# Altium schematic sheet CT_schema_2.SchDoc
size 591 x 347 mm
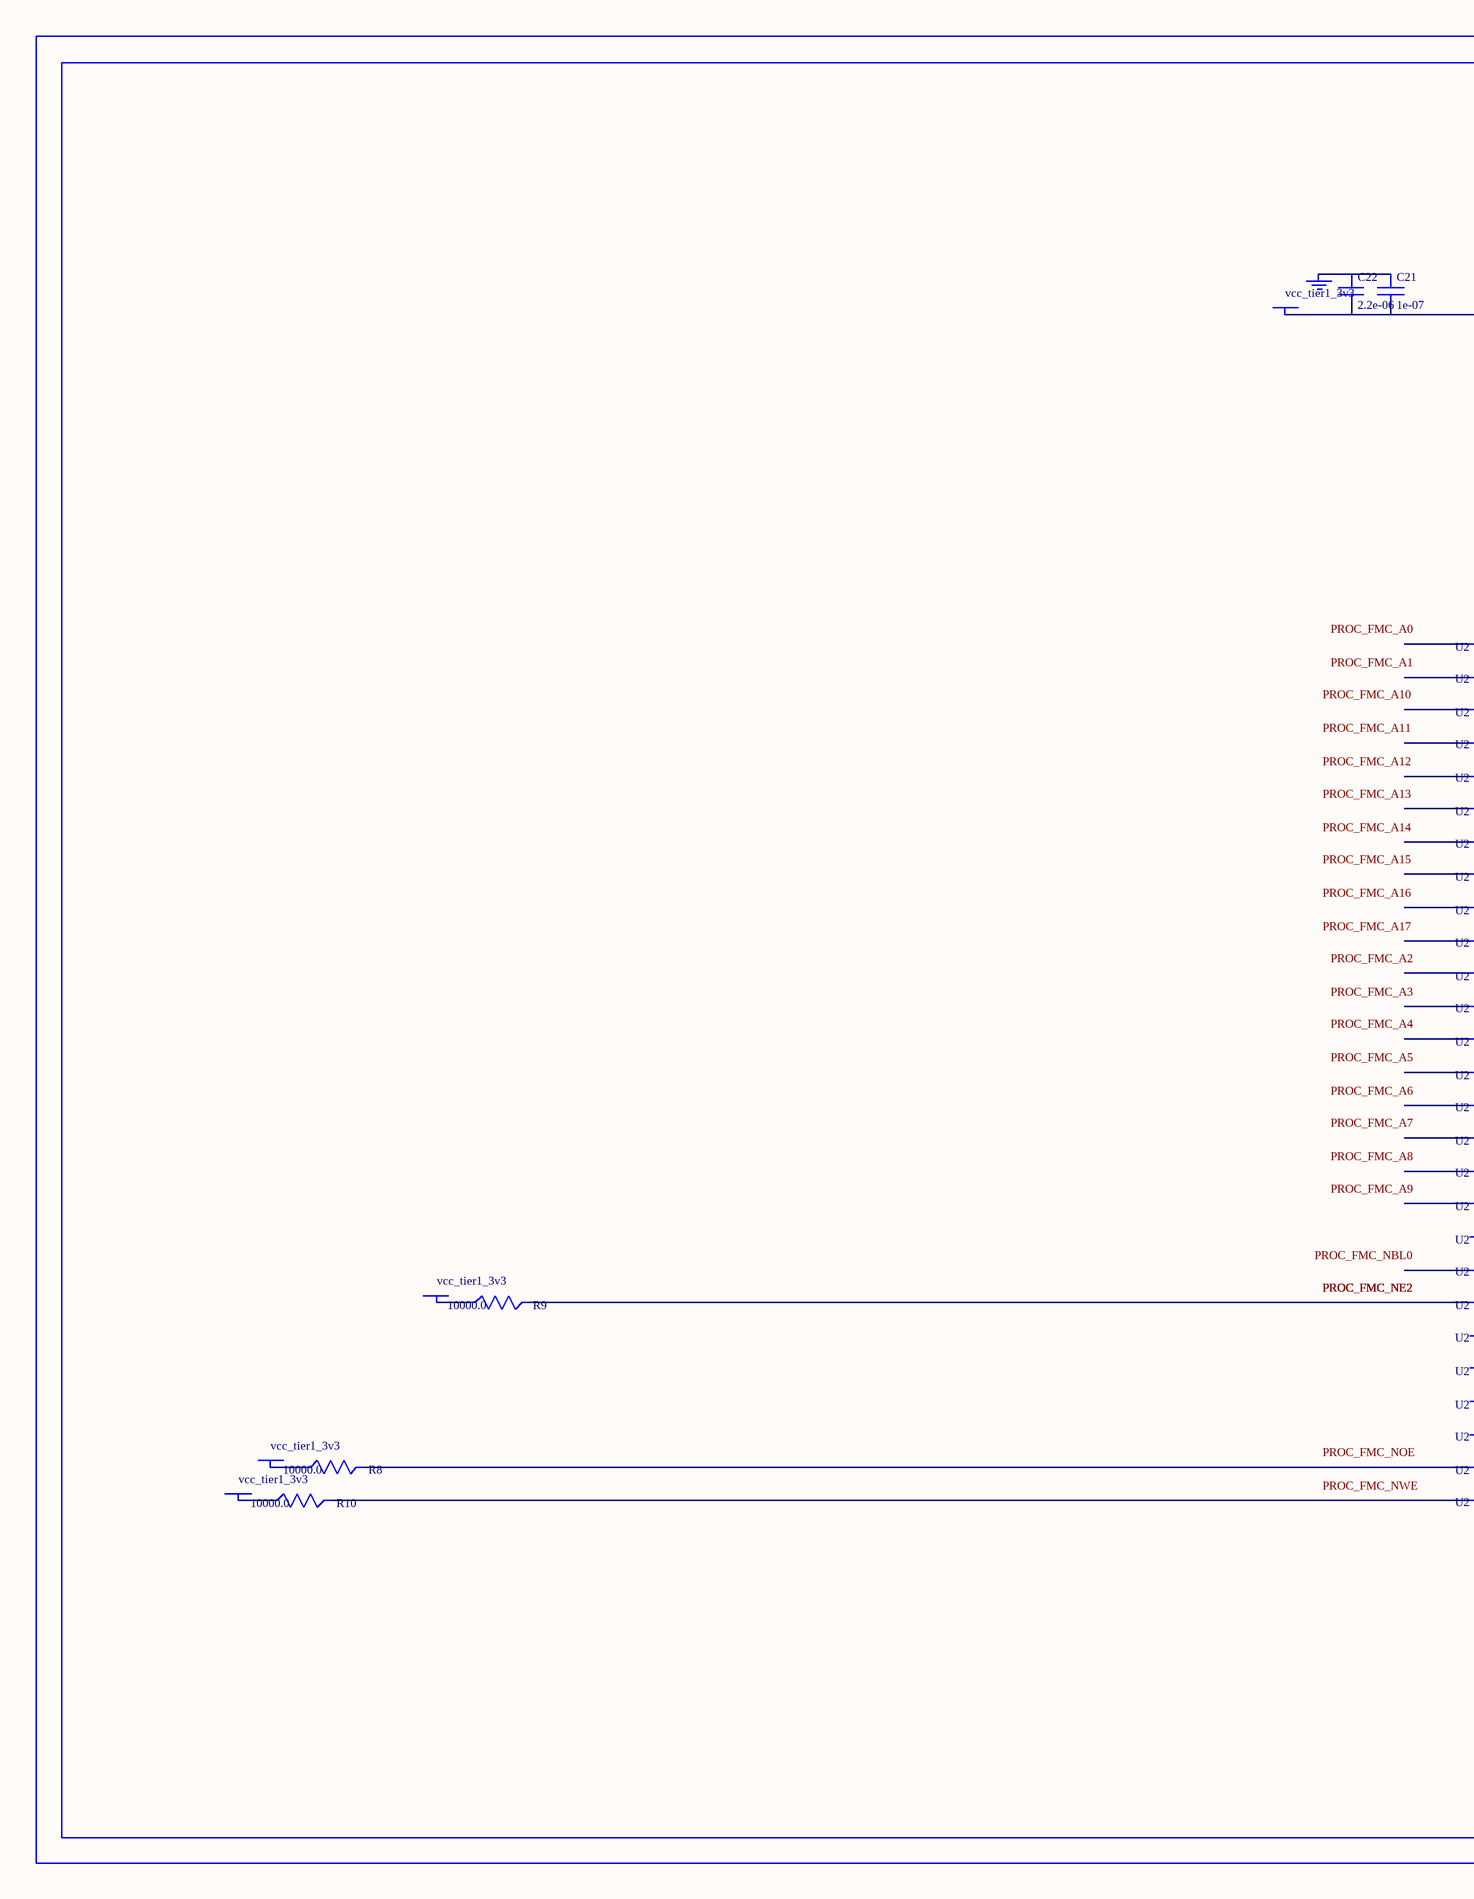
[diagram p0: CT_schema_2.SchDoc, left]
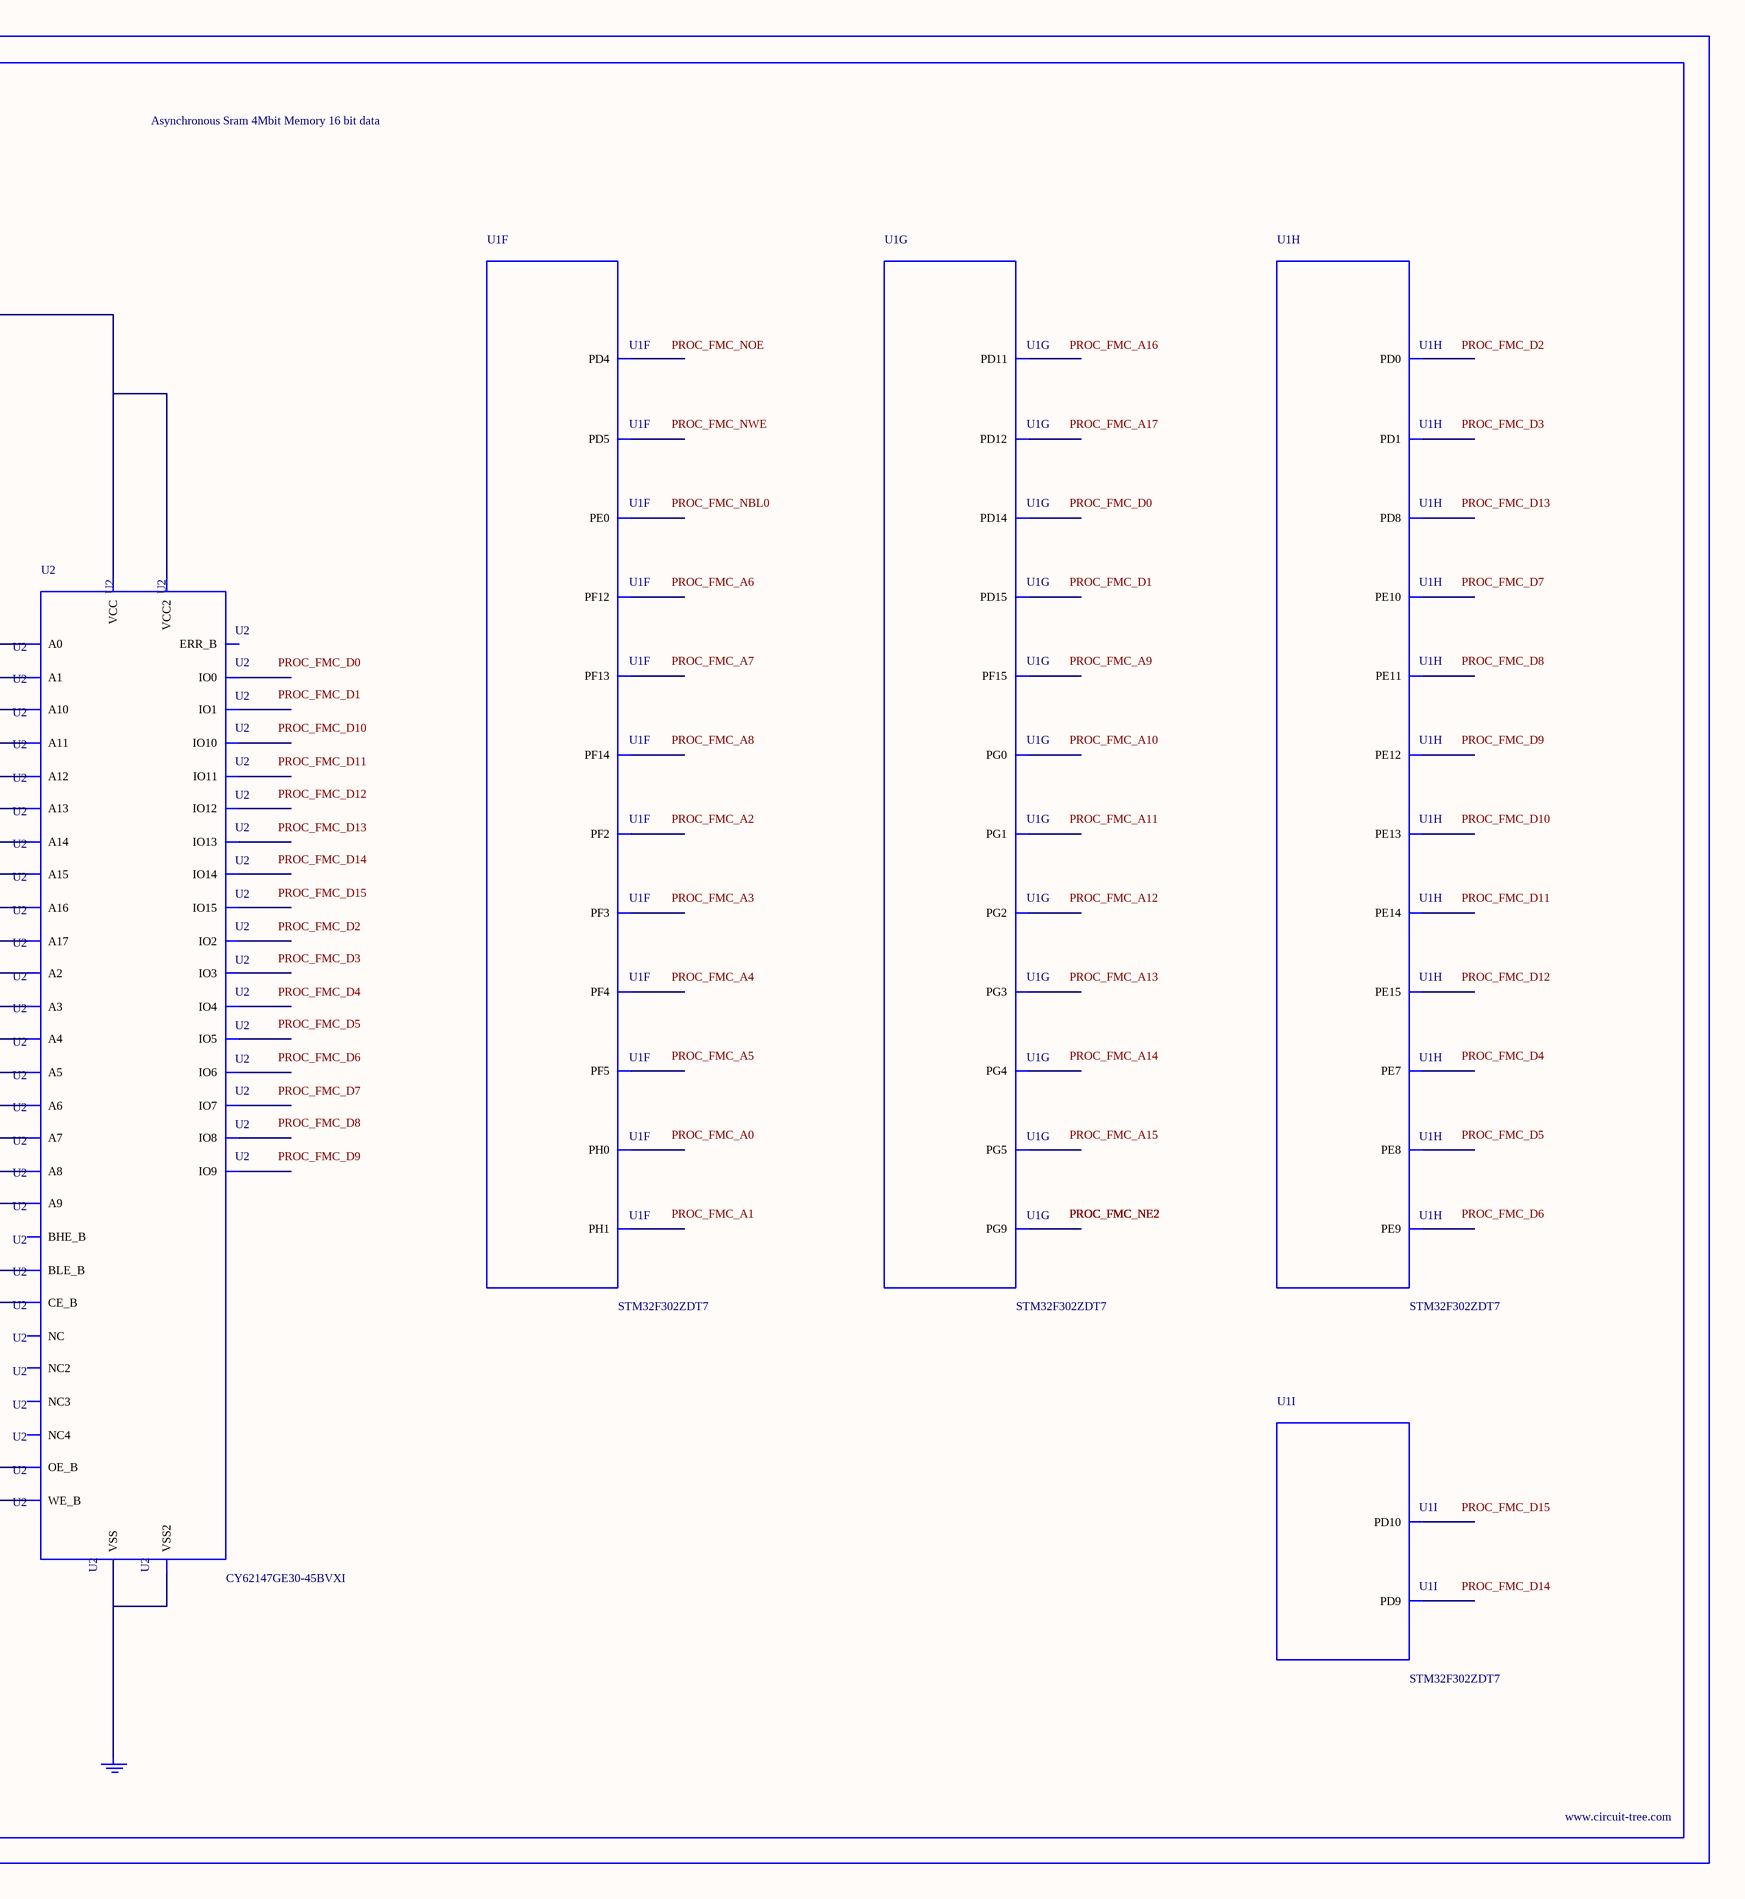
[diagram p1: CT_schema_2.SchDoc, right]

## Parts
BORDER1  (no value)
C21  1e-07  [C0402]
C22  2.2e-06  [C0603]
GND_INSTANCE_1_0  (no value)
GND_INSTANCE_1_1  (no value)
POWER_INSTANCE_1_0  vcc_tier1_3v3
POWER_INSTANCE_1_1  vcc_tier1_3v3
POWER_INSTANCE_1_2  vcc_tier1_3v3
POWER_INSTANCE_1_3  vcc_tier1_3v3
R8  10000.0  [R0603]
R9  10000.0  [R0603]
R10  10000.0  [R0603]
U1  STM32F302ZDT7  [LQFP144]  (parts F,G,H,I of 12)
U2  CY62147GE30-45BVXI  [VFBGA48]

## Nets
NetC21_1: C21.1 C22.1 GND_INSTANCE_1_0.0(GND)
NetC21_2: C21.2 C22.2 POWER_INSTANCE_1_0.0(PWR) U2.D6(VCC) U2.E1(VCC2)
NetGND_INSTANCE_1_1_0: GND_INSTANCE_1_1.0(GND) U2.D1(VSS) U2.E6(VSS2)
NetPOWER_INSTANCE_1_1_0: POWER_INSTANCE_1_1.0(PWR) R8.1
NetPOWER_INSTANCE_1_2_0: POWER_INSTANCE_1_2.0(PWR) R9.1
NetPOWER_INSTANCE_1_3_0: POWER_INSTANCE_1_3.0(PWR) R10.1
NetR8_2: R8.2 U2.A2(OE_B)
NetR9_2: R9.2 U2.B5(CE_B)
NetR10_2: R10.2 U2.G5(WE_B)

Not connected (* = marked no-connect by the designer): U1 10(PH0) 11(PH1) 12(PF2) 13(PF3) 14(PF4) 15(PF5) 50(PF12) 53(PF13) 54(PF14) 55(PF15) 56(PG0) 57(PG1) 58(PE7) 59(PE8) 60(PE9) 63(PE10) 64(PE11) 65(PE12) 66(PE13) 67(PE14) 68(PE15) 77(PD8) 78(PD9) 79(PD10) 80(PD11) 81(PD12) 85(PD14) 86(PD15) 87(PG2) 88(PG3) 89(PG4) 90(PG5) 114(PD0) 115(PD1) 118(PD4) 119(PD5) 124(PG9) 141(PE0); U2 A1(BLE_B) A3(A0) A4(A1) A5(A2) A6(NC) B1(IO8) B2(BHE_B) B3(A3) B4(A4) B6(IO0) C1(IO9) C2(IO10) C3(A5) C4(A6) C5(IO1) C6(IO2) D2(IO11) D3(A17) D4(A7) D5(IO3) E2(IO12) E3(ERR_B) E4(A16) E5(IO4) F1(IO14) F2(IO13) F3(A14) F4(A15) F5(IO5) F6(IO6) G1(IO15) G2(NC2) G3(A12) G4(A13) G6(IO7) H1(NC3) H2(A8) H3(A9) H4(A10) H5(A11) H6(NC4)

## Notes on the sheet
- Labels drawn without touching a wire or pin: PROC_FMC_A0, PROC_FMC_A1, PROC_FMC_A2, PROC_FMC_A3, PROC_FMC_A4, PROC_FMC_A5, PROC_FMC_A6, PROC_FMC_A7, PROC_FMC_A8, PROC_FMC_A9, PROC_FMC_A10, PROC_FMC_A11, PROC_FMC_A12, PROC_FMC_A13, PROC_FMC_A14, PROC_FMC_A15, PROC_FMC_A16, PROC_FMC_A17, PROC_FMC_D0, PROC_FMC_D1, PROC_FMC_D2, PROC_FMC_D3, PROC_FMC_D4, PROC_FMC_D5, PROC_FMC_D6, PROC_FMC_D7, PROC_FMC_D8, PROC_FMC_D9, PROC_FMC_D10, PROC_FMC_D11, PROC_FMC_D12, PROC_FMC_D13, PROC_FMC_D14, PROC_FMC_D15, PROC_FMC_NBL0, PROC_FMC_NOE, PROC_FMC_NWE

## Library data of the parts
BORDER1 = BORDER_PAGE1
C21 = C0402C104K3RACTU
C22 = C0603C225K8RACTU
GND_INSTANCE_1_0 GND_INSTANCE_1_1 = GND
POWER_INSTANCE_1_0-POWER_INSTANCE_1_3 = PWR
R8-R10 = RC0603JR-0710KL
